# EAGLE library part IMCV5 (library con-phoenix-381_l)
Invertierter Mini-Combicon 3.81mm vertikal 5-polig IMCV 1,5/5-G-3,81 (ohne Gegenstecker)
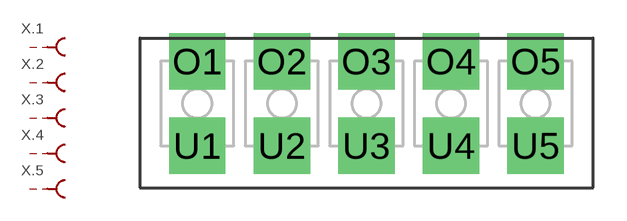
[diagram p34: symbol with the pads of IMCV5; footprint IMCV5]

Designator prefix X; gates .3=MCBU .2=MCBU .1=MCBU .4=MCBU .5=MCBU

## IMCV5  [IMCV5]
O1  .1:S  pas
O2  .2:S  pas
O3  .3:S  pas
O4  .4:S  pas
O5  .5:S  pas
U1  .1:SK  pas
U2  .2:SK  pas
U3  .3:SK  pas
U4  .4:SK  pas
U5  .5:SK  pas

## Footprint IMCV5 (pad centres in mm)
Mini-Combicon 3.81mm vertical 6-polig invertiert (ohne Gegenstecker)
drill 1.3 pad 2.54 square: O1 -7.62,1.905; O2 -3.81,1.905; O3 0,1.905; O4 3.81,1.905; O5 7.62,1.905; U1 -7.62,-1.905; U2 -3.81,-1.905; U3 0,-1.905; U4 3.81,-1.905; U5 7.62,-1.905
